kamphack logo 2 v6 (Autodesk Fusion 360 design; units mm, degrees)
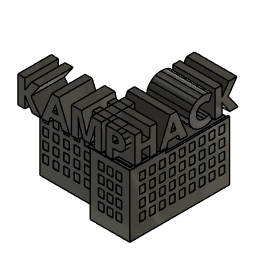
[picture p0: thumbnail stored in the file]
parameter "textDistance" = 1
parameter "extrude" = 3
canvas "Canvas1"
sketch "Sketch1" plane through (0, 0, 0) normal (0, 0, 1) x axis (1, 0, 0)
  line L1 (15, 4.7309) -> (3.3106, 4.7309)
  line L2 (15, 0) -> (15, 4.7309)
  line L3 (3.3106, 0) -> (15, 0)
  line L4 (3.3106, 4.7309) -> (3.3106, 0)
  line L5 (15, 4.7309) -> (10.4685, 4.7309)
  line L6 (15, 10.3904) -> (15, 4.7309)
  line L7 (10.4685, 10.3904) -> (15, 10.3904)
  line L8 (10.4685, 4.7309) -> (10.4685, 10.3904)
  line L9 (15, 0) -> (10.5084, 0)
  line L10 (15, -1.5) -> (15, 0)
  line L11 (10.5084, -1.5) -> (15, -1.5)
  line L12 (10.5084, 0) -> (10.5084, -1.5)
  line L13 (15, -1) -> (10.5084, -1)
  line L14 (15, -1.5) -> (15, -1)
  line L15 (10.5084, -1.5) -> (15, -1.5)
  line L16 (10.5084, -1) -> (10.5084, -1.5)
  line L17 (15, -1.5) -> (14.5, -1.5)
  line L18 (15, 2.4512) -> (15, -1.5)
  line L19 (14.5, 2.4512) -> (15, 2.4512)
  line L20 (14.5, -1.5) -> (14.5, 2.4512)
  point P6 (10.4685, 4.7309)
  point P10 (10.5084, 0)
  point P14 (10.5084, -1)
  point P19 (15, 2.4512)
  point P17 (14.5, -1.5)
  horizontal L1
  vertical L2
  horizontal L3
  vertical L4
  horizontal L5
  vertical L6
  horizontal L7
  vertical L8
  coincident L1 P6
  horizontal L9
  vertical L10
  horizontal L11
  vertical L12
  coincident L3 P10
  horizontal L13
  vertical L14
  horizontal L15
  vertical L16
  coincident L12 P14
  horizontal L17
  vertical L18
  horizontal L19
  vertical L20
  coincident L2 P19
  coincident L11 P17
extrude "Extrude1" new body sketch "Sketch1" along normal blind 6.5
extrude "Extrude2" add of existing geometry blind 0.2 Side1WallThickness 0.2
sketch "Sketch2" plane through (0, 0, 6.7) normal (0, 0, 1) x axis (-1, 0, 0)
  line L1 (-10.7084, -0.2) -> (-10.7084, 1.3)
  line L2 (-3.5106, -0.2) -> (-10.7084, -0.2)
  line L3 (-3.5106, -4.5309) -> (-3.5106, -0.2)
  line L4 (-10.6685, -4.5309) -> (-3.5106, -4.5309)
  line L5 (-10.6685, -10.1904) -> (-10.6685, -4.5309)
  line L6 (-14.8, -10.1904) -> (-10.6685, -10.1904)
  line L7 (-14.8, 1.3) -> (-14.8, -10.1904)
  line L8 (-10.7084, 1.3) -> (-14.8, 1.3)
  line L9 (-15, 1.5) -> (-10.5084, 1.5)
  line L10 (-15, -10.3904) -> (-15, 1.5)
  line L11 (-10.4685, -10.3904) -> (-15, -10.3904)
  line L12 (-10.4685, -4.7309) -> (-10.4685, -10.3904)
  line L13 (-3.3106, -4.7309) -> (-10.4685, -4.7309)
  line L14 (-3.3106, 0) -> (-3.3106, -4.7309)
  line L15 (-10.5084, 0) -> (-3.3106, 0)
  line L16 (-10.5084, 1.5) -> (-10.5084, 0)
  line L17 (-10.5084, 1.4) -> (-10.6, 1.4)
  line L18 (-15, 1.5) -> (-10.5084, 1.5)
  line L19 (-14.9, 1.4) -> (-10.6, 1.4)
  line L20 (-14.9, -2.55) -> (-14.9, 1.4)
  line L21 (-15, -2.55) -> (-14.9, -2.55)
  line L22 (-15, 1.5) -> (-15, -2.55)
  point P19 (-10.5084, 1.4)
  point P10 (-10.5084, 1.5)
  point P20 (-10.5084, 1.5)
  point P11 (-15, 1.5)
  point P21 (-15, 1.5)
  point P24 (-15, -2.55)
  point P25 (-15, 1.5)
  coincident L16 P19
  perpendicular L16 L17
  coincident P10 P20
  coincident P11 P21
  perpendicular L10 L19
  perpendicular L19 L20
  coincident L10 P24
  perpendicular L10 L21
  coincident P11 P25
extrude "Extrude3" add sketch "Sketch2" profile of L9 L10 L16 L17 L18 L19 L20 L21 L22 along normal blind 0.65
sketch "Sketch7" plane through (0, 0, 7.35) normal (0, 0, 1) x axis (-1, 0, 0)
  line L1 (-10.5084, 1.4) -> (-14.9, 1.4)
  line L2 (-10.5084, 1.5) -> (-10.5084, 1.4)
  line L3 (-15, 1.5) -> (-10.5084, 1.5)
  line L4 (-15, -2.55) -> (-15, 1.5)
  line L5 (-14.9, -2.55) -> (-15, -2.55)
  line L6 (-14.9, 1.4) -> (-14.9, -2.55)
  line L7 (-15.3, -2.55) -> (-15, -2.55)
  line L8 (-15.3, 1.5) -> (-15.3, -2.55)
  line L9 (-15, 1.5) -> (-15.3, 1.5)
  line L10 (-15, -2.55) -> (-15, 1.5)
  line L11 (-10.5095, 1.5) -> (-15, 1.5)
  line L12 (-10.5095, 1.8) -> (-10.5095, 1.5)
  line L13 (-15, 1.8) -> (-10.5095, 1.8)
  line L14 (-15, 1.5) -> (-15, 1.8)
  line L15 (-15.3, 1.8) -> (-15, 1.8)
  line L16 (-15.3, 1.5) -> (-15.3, 1.8)
  line L17 (-15, 1.5) -> (-15.3, 1.5)
  line L18 (-15, 1.8) -> (-15, 1.5)
  point P6 (-15, -2.55)
  point P8 (-15, -2.55)
  point P9 (-15.3, -2.55)
  point P11 (-15, 1.5)
  point P14 (-15, 1.8)
  horizontal L7
  vertical L8
  horizontal L9
  vertical L10
  coincident P6 P8
  horizontal L11
  vertical L12
  horizontal L13
  vertical L14
  horizontal L15
  vertical L16
  horizontal L17
  vertical L18
  dimension "d13" distance P8 P9 = 0.3
  dimension "d14" distance P11 P14 = 0.3
extrude "Extrude6" add sketch "Sketch7" profile of L3 L4 L7 L8 L9 L10 L11 L12 L13 L14 L15 L16 L17 L18 against normal blind 0.03
sketch "Sketch8" plane through (0, -1.5, 0) normal (0, -1, 0) x axis (1, 0, 0)
  line L1 (10.5095, 7.35) -> (10.5095, 7.32)
  line L2 (10.5084, 7.35) -> (10.5095, 7.35)
  line L3 (10.5084, 0) -> (10.5084, 7.35)
  line L4 (15, 0) -> (10.5084, 0)
  line L5 (15, 7.32) -> (15, 0)
  line L6 (10.5095, 7.32) -> (15, 7.32)
  line L7 (12.7542, 0) -> (12.7547, 7.32)
  line L8 (12.4382, 6.2521) -> (13.0711, 6.2521)
  line L9 (12.4382, 5.4181) -> (12.4382, 6.2521)
  line L10 (13.0711, 5.4181) -> (12.4382, 5.4181)
  line L11 (13.0711, 6.2521) -> (13.0711, 5.4181)
  line L12 (12.4382, 5.4181) -> (13.0711, 6.2521)
  line L13 (13.0711, 5.4181) -> (12.4382, 6.2521)
  line L14 (12.0711, 5.4181) -> (11.4382, 5.4181)
  line L15 (12.0711, 6.2521) -> (12.0711, 5.4181)
  line L16 (11.4382, 6.2521) -> (12.0711, 6.2521)
  line L17 (11.4382, 5.4181) -> (11.4382, 6.2521)
  line L18 (14.0711, 5.4181) -> (13.4382, 5.4181)
  line L19 (14.0711, 6.2521) -> (14.0711, 5.4181)
  line L20 (13.4382, 6.2521) -> (14.0711, 6.2521)
  line L21 (13.4382, 5.4181) -> (13.4382, 6.2521)
  line L22 (12.0711, 4.0848) -> (11.4382, 4.0848)
  line L23 (12.0711, 4.9188) -> (12.0711, 4.0848)
  line L24 (11.4382, 4.9188) -> (12.0711, 4.9188)
  line L25 (11.4382, 4.0848) -> (11.4382, 4.9188)
  line L26 (13.0711, 4.0848) -> (12.4382, 4.0848)
  line L27 (13.0711, 4.9188) -> (13.0711, 4.0848)
  line L28 (12.4382, 4.9188) -> (13.0711, 4.9188)
  line L29 (12.4382, 4.0848) -> (12.4382, 4.9188)
  line L30 (14.0711, 4.0848) -> (13.4382, 4.0848)
  line L31 (14.0711, 4.9188) -> (14.0711, 4.0848)
  line L32 (13.4382, 4.9188) -> (14.0711, 4.9188)
  line L33 (13.4382, 4.0848) -> (13.4382, 4.9188)
  line L34 (12.0711, 2.7514) -> (11.4382, 2.7514)
  line L35 (12.0711, 3.5854) -> (12.0711, 2.7514)
  line L36 (11.4382, 3.5854) -> (12.0711, 3.5854)
  line L37 (11.4382, 2.7514) -> (11.4382, 3.5854)
  line L38 (13.0711, 2.7514) -> (12.4382, 2.7514)
  line L39 (13.0711, 3.5854) -> (13.0711, 2.7514)
  line L40 (12.4382, 3.5854) -> (13.0711, 3.5854)
  line L41 (12.4382, 2.7514) -> (12.4382, 3.5854)
  line L42 (14.0711, 2.7514) -> (13.4382, 2.7514)
  line L43 (14.0711, 3.5854) -> (14.0711, 2.7514)
  line L44 (13.4382, 3.5854) -> (14.0711, 3.5854)
  line L45 (13.4382, 2.7514) -> (13.4382, 3.5854)
  line L46 (12.0711, 1.4181) -> (11.4382, 1.4181)
  line L47 (12.0711, 2.2521) -> (12.0711, 1.4181)
  line L48 (11.4382, 2.2521) -> (12.0711, 2.2521)
  line L49 (11.4382, 1.4181) -> (11.4382, 2.2521)
  line L50 (13.0711, 1.4181) -> (12.4382, 1.4181)
  line L51 (13.0711, 2.2521) -> (13.0711, 1.4181)
  line L52 (12.4382, 2.2521) -> (13.0711, 2.2521)
  line L53 (12.4382, 1.4181) -> (12.4382, 2.2521)
  line L54 (14.0711, 1.4181) -> (13.4382, 1.4181)
  line L55 (14.0711, 2.2521) -> (14.0711, 1.4181)
  line L56 (13.4382, 2.2521) -> (14.0711, 2.2521)
  line L57 (13.4382, 1.4181) -> (13.4382, 2.2521)
  line L58 (4.2711, 5.4181) -> (3.6382, 5.4181)
  line L59 (4.2711, 6.2521) -> (4.2711, 5.4181)
  line L60 (3.6382, 6.2521) -> (4.2711, 6.2521)
  line L61 (3.6382, 5.4181) -> (3.6382, 6.2521)
  line L62 (4.8182, 5.4181) -> (4.8182, 6.2521)
  line L63 (5.4511, 5.4181) -> (4.8182, 5.4181)
  line L64 (5.4511, 6.2521) -> (5.4511, 5.4181)
  line L65 (4.8182, 6.2521) -> (5.4511, 6.2521)
  line L66 (5.9982, 5.4181) -> (5.9982, 6.2521)
  line L67 (6.6311, 5.4181) -> (5.9982, 5.4181)
  line L68 (6.6311, 6.2521) -> (6.6311, 5.4181)
  line L69 (5.9982, 6.2521) -> (6.6311, 6.2521)
  line L70 (7.1782, 5.4181) -> (7.1782, 6.2521)
  line L71 (7.8111, 5.4181) -> (7.1782, 5.4181)
  line L72 (7.8111, 6.2521) -> (7.8111, 5.4181)
  line L73 (7.1782, 6.2521) -> (7.8111, 6.2521)
  line L74 (8.3582, 5.4181) -> (8.3582, 6.2521)
  line L75 (8.9911, 5.4181) -> (8.3582, 5.4181)
  line L76 (8.9911, 6.2521) -> (8.9911, 5.4181)
  line L77 (8.3582, 6.2521) -> (8.9911, 6.2521)
  line L78 (9.5382, 5.4181) -> (9.5382, 6.2521)
  line L79 (10.1711, 5.4181) -> (9.5382, 5.4181)
  line L80 (10.1711, 6.2521) -> (10.1711, 5.4181)
  line L81 (9.5382, 6.2521) -> (10.1711, 6.2521)
  line L82 (3.6382, 4.0848) -> (3.6382, 4.9188)
  line L83 (4.2711, 4.0848) -> (3.6382, 4.0848)
  line L84 (4.2711, 4.9188) -> (4.2711, 4.0848)
  line L85 (3.6382, 4.9188) -> (4.2711, 4.9188)
  line L86 (4.8182, 4.0848) -> (4.8182, 4.9188)
  line L87 (5.4511, 4.0848) -> (4.8182, 4.0848)
  line L88 (5.4511, 4.9188) -> (5.4511, 4.0848)
  line L89 (4.8182, 4.9188) -> (5.4511, 4.9188)
  line L90 (5.9982, 4.0848) -> (5.9982, 4.9188)
  line L91 (6.6311, 4.0848) -> (5.9982, 4.0848)
  line L92 (6.6311, 4.9188) -> (6.6311, 4.0848)
  line L93 (5.9982, 4.9188) -> (6.6311, 4.9188)
  line L94 (7.1782, 4.0848) -> (7.1782, 4.9188)
  line L95 (7.8111, 4.0848) -> (7.1782, 4.0848)
  line L96 (7.8111, 4.9188) -> (7.8111, 4.0848)
  line L97 (7.1782, 4.9188) -> (7.8111, 4.9188)
  line L98 (8.3582, 4.0848) -> (8.3582, 4.9188)
  line L99 (8.9911, 4.0848) -> (8.3582, 4.0848)
  line L100 (8.9911, 4.9188) -> (8.9911, 4.0848)
  line L101 (8.3582, 4.9188) -> (8.9911, 4.9188)
  line L102 (9.5382, 4.0848) -> (9.5382, 4.9188)
  line L103 (10.1711, 4.0848) -> (9.5382, 4.0848)
  line L104 (10.1711, 4.9188) -> (10.1711, 4.0848)
  line L105 (9.5382, 4.9188) -> (10.1711, 4.9188)
  line L106 (3.6382, 2.7514) -> (3.6382, 3.5854)
  line L107 (4.2711, 2.7514) -> (3.6382, 2.7514)
  line L108 (4.2711, 3.5854) -> (4.2711, 2.7514)
  line L109 (3.6382, 3.5854) -> (4.2711, 3.5854)
  line L110 (4.8182, 2.7514) -> (4.8182, 3.5854)
  line L111 (5.4511, 2.7514) -> (4.8182, 2.7514)
  line L112 (5.4511, 3.5854) -> (5.4511, 2.7514)
  line L113 (4.8182, 3.5854) -> (5.4511, 3.5854)
  line L114 (5.9982, 2.7514) -> (5.9982, 3.5854)
  line L115 (6.6311, 2.7514) -> (5.9982, 2.7514)
  line L116 (6.6311, 3.5854) -> (6.6311, 2.7514)
  line L117 (5.9982, 3.5854) -> (6.6311, 3.5854)
  line L118 (7.1782, 2.7514) -> (7.1782, 3.5854)
  line L119 (7.8111, 2.7514) -> (7.1782, 2.7514)
  line L120 (7.8111, 3.5854) -> (7.8111, 2.7514)
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  point P8 (12.7547, 7.32)
  point P9 (12.7542, 0)
  point P14 (12.7546, 5.8351)
  midpoint L6 P8
  midpoint L4 P9
  horizontal L8
  perpendicular L8 L9
  parallel L8 L10
  parallel L9 L11
  coincident L12 P14
  coincident L13 P14
  coincident L7 P14
  horizontal L60
  perpendicular L60 L61
  parallel L58 L60
  parallel L59 L61
  dimension "d19" R-Pattern1-uDistance = 1
  dimension "d20" R-Pattern1-vDistance = -4
  dimension "d23" R-Pattern2-uDistance = 5.9
  dimension "d24" R-Pattern2-vDistance = -4
extrude "Extrude7" cut sketch "Sketch8" profile of L8 L9 L10 L11 L14 L15 L16 L17 L18 L19 L20 L21 L22 L23 L24 L25 L26 L27 L28 L29 L30 L31 L32 L33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 against normal blind 0.03
extrude "Extrude8" cut sketch "Sketch8" against normal blind 1.53
sketch "Sketch9" plane through (15, 0, 0) normal (1, 0, 0) x axis (0, 1, 0)
  line L1 (-1.5, 7.32) -> (2.55, 7.32)
  line L2 (-1.5, 0) -> (-1.5, 7.32)
  line L3 (10.3904, 0) -> (-1.5, 0)
  line L4 (10.3904, 6.7) -> (10.3904, 0)
  line L5 (2.55, 6.7) -> (10.3904, 6.7)
  line L6 (2.55, 7.32) -> (2.55, 6.7)
  line L7 (9.2574, 6.25) -> (8.63, 6.25)
  line L8 (9.2574, 5.4185) -> (9.2574, 6.25)
  line L9 (8.63, 5.4185) -> (9.2574, 5.4185)
  line L10 (8.63, 6.25) -> (8.63, 5.4185)
  line L11 (8.1324, 6.25) -> (7.505, 6.25)
  line L12 (7.505, 6.25) -> (7.505, 5.4185)
  line L13 (7.505, 5.4185) -> (8.1324, 5.4185)
  line L14 (8.1324, 5.4185) -> (8.1324, 6.25)
  line L15 (7.0074, 6.25) -> (6.38, 6.25)
  line L16 (6.38, 6.25) -> (6.38, 5.4185)
  line L17 (6.38, 5.4185) -> (7.0074, 5.4185)
  line L18 (7.0074, 5.4185) -> (7.0074, 6.25)
  line L19 (5.8824, 6.25) -> (5.255, 6.25)
  line L20 (5.255, 6.25) -> (5.255, 5.4185)
  line L21 (5.255, 5.4185) -> (5.8824, 5.4185)
  line L22 (5.8824, 5.4185) -> (5.8824, 6.25)
  line L23 (4.7574, 6.25) -> (4.13, 6.25)
  line L24 (4.13, 6.25) -> (4.13, 5.4185)
  line L25 (4.13, 5.4185) -> (4.7574, 5.4185)
  line L26 (4.7574, 5.4185) -> (4.7574, 6.25)
  line L27 (3.6324, 6.25) -> (3.005, 6.25)
  line L28 (3.005, 6.25) -> (3.005, 5.4185)
  line L29 (3.005, 5.4185) -> (3.6324, 5.4185)
  line L30 (3.6324, 5.4185) -> (3.6324, 6.25)
  line L31 (2.5074, 6.25) -> (1.88, 6.25)
  line L32 (1.88, 6.25) -> (1.88, 5.4185)
  line L33 (1.88, 5.4185) -> (2.5074, 5.4185)
  line L34 (2.5074, 5.4185) -> (2.5074, 6.25)
  line L35 (1.3824, 6.25) -> (0.755, 6.25)
  line L36 (0.755, 6.25) -> (0.755, 5.4185)
  line L37 (0.755, 5.4185) -> (1.3824, 5.4185)
  line L38 (1.3824, 5.4185) -> (1.3824, 6.25)
  line L39 (0.2574, 6.25) -> (-0.37, 6.25)
  line L40 (-0.37, 6.25) -> (-0.37, 5.4185)
  line L41 (-0.37, 5.4185) -> (0.2574, 5.4185)
  line L42 (0.2574, 5.4185) -> (0.2574, 6.25)
  line L43 (9.2574, 4.9167) -> (8.63, 4.9167)
  line L44 (8.63, 4.9167) -> (8.63, 4.0852)
  line L45 (8.63, 4.0852) -> (9.2574, 4.0852)
  line L46 (9.2574, 4.0852) -> (9.2574, 4.9167)
  line L47 (8.1324, 4.9167) -> (7.505, 4.9167)
  line L48 (7.505, 4.9167) -> (7.505, 4.0852)
  line L49 (7.505, 4.0852) -> (8.1324, 4.0852)
  line L50 (8.1324, 4.0852) -> (8.1324, 4.9167)
  line L51 (7.0074, 4.9167) -> (6.38, 4.9167)
  line L52 (6.38, 4.9167) -> (6.38, 4.0852)
  line L53 (6.38, 4.0852) -> (7.0074, 4.0852)
  line L54 (7.0074, 4.0852) -> (7.0074, 4.9167)
  line L55 (5.8824, 4.9167) -> (5.255, 4.9167)
  line L56 (5.255, 4.9167) -> (5.255, 4.0852)
  line L57 (5.255, 4.0852) -> (5.8824, 4.0852)
  line L58 (5.8824, 4.0852) -> (5.8824, 4.9167)
  line L59 (4.7574, 4.9167) -> (4.13, 4.9167)
  line L60 (4.13, 4.9167) -> (4.13, 4.0852)
  line L61 (4.13, 4.0852) -> (4.7574, 4.0852)
  line L62 (4.7574, 4.0852) -> (4.7574, 4.9167)
  line L63 (3.6324, 4.9167) -> (3.005, 4.9167)
  line L64 (3.005, 4.9167) -> (3.005, 4.0852)
  line L65 (3.005, 4.0852) -> (3.6324, 4.0852)
  line L66 (3.6324, 4.0852) -> (3.6324, 4.9167)
  line L67 (2.5074, 4.9167) -> (1.88, 4.9167)
  line L68 (1.88, 4.9167) -> (1.88, 4.0852)
  line L69 (1.88, 4.0852) -> (2.5074, 4.0852)
  line L70 (2.5074, 4.0852) -> (2.5074, 4.9167)
  line L71 (1.3824, 4.9167) -> (0.755, 4.9167)
  line L72 (0.755, 4.9167) -> (0.755, 4.0852)
  line L73 (0.755, 4.0852) -> (1.3824, 4.0852)
  line L74 (1.3824, 4.0852) -> (1.3824, 4.9167)
  line L75 (0.2574, 4.9167) -> (-0.37, 4.9167)
  line L76 (-0.37, 4.9167) -> (-0.37, 4.0852)
  line L77 (-0.37, 4.0852) -> (0.2574, 4.0852)
  line L78 (0.2574, 4.0852) -> (0.2574, 4.9167)
  line L79 (9.2574, 3.5833) -> (8.63, 3.5833)
  line L80 (8.63, 3.5833) -> (8.63, 2.7519)
  line L81 (8.63, 2.7519) -> (9.2574, 2.7519)
  line L82 (9.2574, 2.7519) -> (9.2574, 3.5833)
  line L83 (8.1324, 3.5833) -> (7.505, 3.5833)
  line L84 (7.505, 3.5833) -> (7.505, 2.7519)
  line L85 (7.505, 2.7519) -> (8.1324, 2.7519)
  line L86 (8.1324, 2.7519) -> (8.1324, 3.5833)
  line L87 (7.0074, 3.5833) -> (6.38, 3.5833)
  line L88 (6.38, 3.5833) -> (6.38, 2.7519)
  line L89 (6.38, 2.7519) -> (7.0074, 2.7519)
  line L90 (7.0074, 2.7519) -> (7.0074, 3.5833)
  line L91 (5.8824, 3.5833) -> (5.255, 3.5833)
  line L92 (5.255, 3.5833) -> (5.255, 2.7519)
  line L93 (5.255, 2.7519) -> (5.8824, 2.7519)
  line L94 (5.8824, 2.7519) -> (5.8824, 3.5833)
  line L95 (4.7574, 3.5833) -> (4.13, 3.5833)
  line L96 (4.13, 3.5833) -> (4.13, 2.7519)
  line L97 (4.13, 2.7519) -> (4.7574, 2.7519)
  line L98 (4.7574, 2.7519) -> (4.7574, 3.5833)
  line L99 (3.6324, 3.5833) -> (3.005, 3.5833)
  line L100 (3.005, 3.5833) -> (3.005, 2.7519)
  line L101 (3.005, 2.7519) -> (3.6324, 2.7519)
  line L102 (3.6324, 2.7519) -> (3.6324, 3.5833)
  line L103 (2.5074, 3.5833) -> (1.88, 3.5833)
  line L104 (1.88, 3.5833) -> (1.88, 2.7519)
  line L105 (1.88, 2.7519) -> (2.5074, 2.7519)
  line L106 (2.5074, 2.7519) -> (2.5074, 3.5833)
  line L107 (1.3824, 3.5833) -> (0.755, 3.5833)
  line L108 (0.755, 3.5833) -> (0.755, 2.7519)
  line L109 (0.755, 2.7519) -> (1.3824, 2.7519)
  line L110 (1.3824, 2.7519) -> (1.3824, 3.5833)
  line L111 (0.2574, 3.5833) -> (-0.37, 3.5833)
  line L112 (-0.37, 3.5833) -> (-0.37, 2.7519)
  line L113 (-0.37, 2.7519) -> (0.2574, 2.7519)
  line L114 (0.2574, 2.7519) -> (0.2574, 3.5833)
  line L115 (9.2574, 2.25) -> (8.63, 2.25)
  line L116 (8.63, 2.25) -> (8.63, 1.4185)
  line L117 (8.63, 1.4185) -> (9.2574, 1.4185)
  line L118 (9.2574, 1.4185) -> (9.2574, 2.25)
  line L119 (8.1324, 2.25) -> (7.505, 2.25)
  line L120 (7.505, 2.25) -> (7.505, 1.4185)
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  horizontal L7
  vertical L8
  horizontal L9
  vertical L10
  dimension "d31" R-Pattern1-uDistance = -9
  dimension "d32" R-Pattern1-vDistance = -4
extrude "Extrude9" cut sketch "Sketch9" against normal blind 0.03
work_plane "WorkPlane1" AlongDistance 1 (= "textDistance")
work_plane "WorkPlane2" AlongDistance 1 (= "textDistance")
sketch "Sketch11" plane through (0, -2.5, 0) normal (0, -1, 0) x axis (-1, 0, 0)
  dimension "d38" = 4
sketch "Sketch12" plane through (16, 0, 0) normal (1, 0, 0) x axis (0, 1, 0)
  dimension "d39" = 4
extrude "Extrude10" new body sketch "Sketch11" along normal blind 3 (= "extrude")
extrude "Extrude11" new body sketch "Sketch12" along normal blind 3 (= "extrude")
component_from_bodies "Body->Comp1"
copy_paste_bodies "CutPasteBodies1"
component_from_bodies "Body->Comp2"
copy_paste_bodies "CutPasteBodies1"
move "Move1"
scale "Scale1" ScaleFactor 1.721
move "Move2"
offset_faces "OffsetFaces1" distance 18
offset_faces "OffsetFaces1" distance 17
scale "Scale1" ScaleX 1 ScaleY 1.3 ScaleZ 1.3
scale "Scale1" ScaleX 1.3 ScaleZ 1.3
offset_faces "OffsetFaces2" distance -14.5
offset_faces "OffsetFaces2" distance -12.5
offset_faces "OffsetFaces3" distance 1
offset_faces "OffsetFaces3" distance -0.25
position "Position1"
extrude "Extrude1" cut of existing geometry blind -4
offset_faces "OffsetFaces2" distance -1
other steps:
base_feature "Base Feature1"
base_feature "Base Feature1"
base_feature "Base Feature2"
base_feature "Base Feature2"
create_component "CreateComponent1"
remove_body "RemoveBody1"
remove_body "RemoveBody2"
remove_body "RemoveBody3"
remove_body "RemoveBody4"
create_component "CreateComponent2"
remove_body "RemoveBody5"
remove_body "RemoveBody6"
remove_body "RemoveBody7"
remove_body "RemoveBody8"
